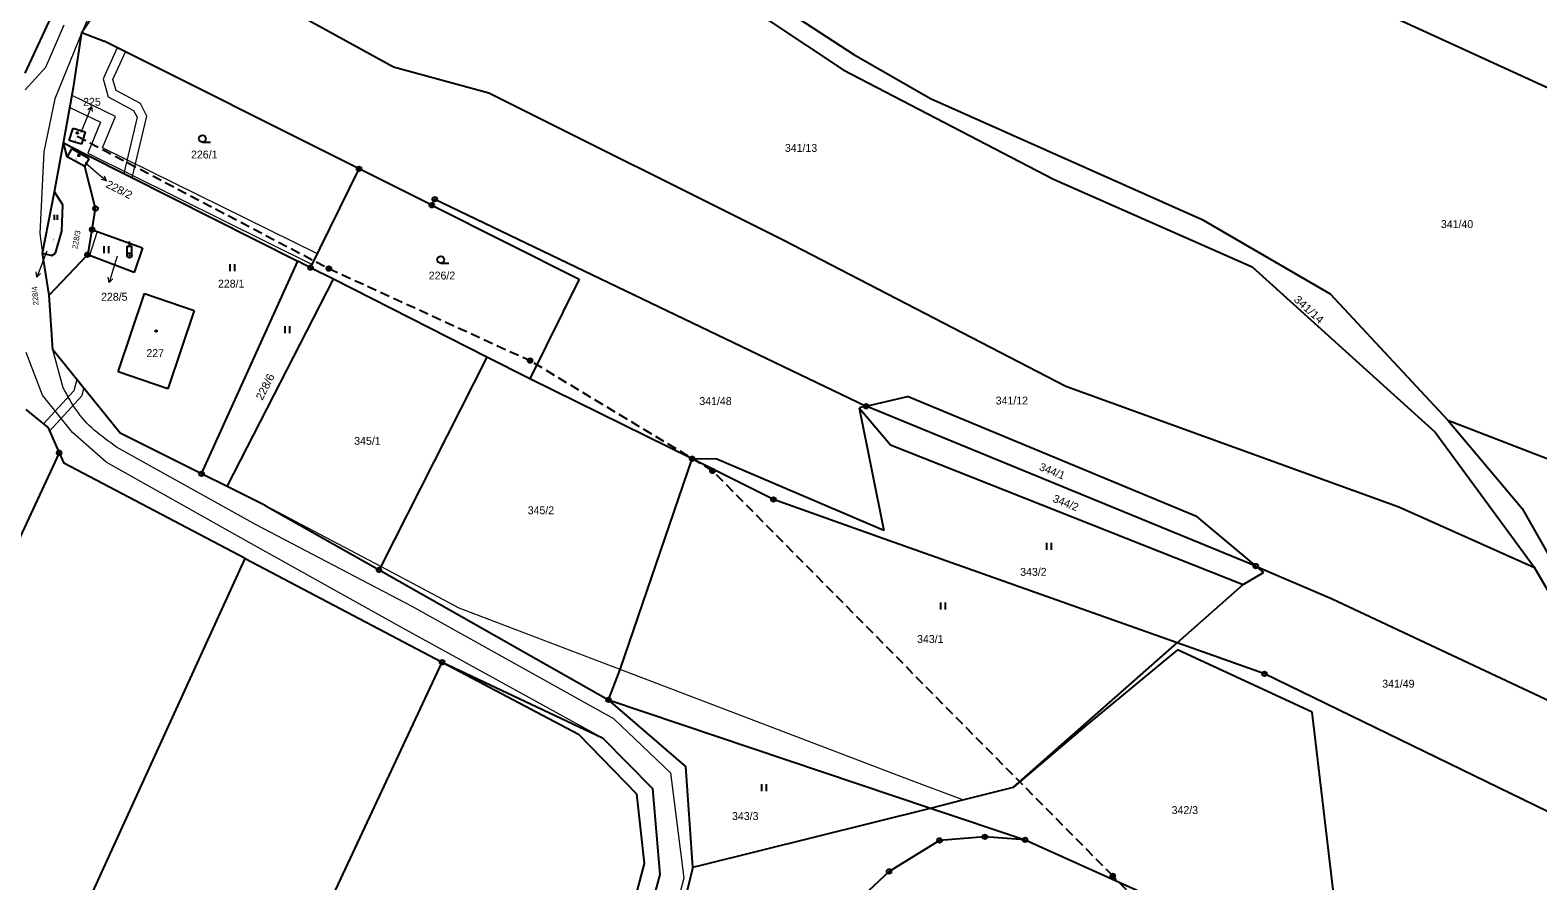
# Model space of a CAD drawing. Extents: x -504006 to -501322, y -1128098 to -1124665.
# Drawn here: x -502552.5 to -502227.9, y -1127007.5 to -1126824.4 of the extents above; entities that cross this region are included whole.
import ezdxf
from ezdxf.enums import TextEntityAlignment as Align

# ---------------------------------------------------------------- set-up
doc = ezdxf.new("R2010")
doc.units = 0
doc.header["$LTSCALE"] = 0.68
doc.linetypes.add('MEDIUM_DASHED', pattern=[4.5, 3, -1.5])
for name, color, linetype, lineweight in [('1', 7, 'Continuous', 25), ('13', 7, 'Continuous', 13), ('3', 7, 'Continuous', 25), ('4', 7, 'Continuous', 13), ('5', 7, 'Continuous', 25), ('6', 7, 'Continuous', 25), ('7', 7, 'Continuous', 13), ('8', 7, 'Continuous', 25)]:
    doc.layers.add(name, color=color, linetype=linetype, lineweight=lineweight)
doc.layers.add('2', color=7, linetype='Continuous')

msp = doc.modelspace()

# ---------------------------------------------------------------- linework, layer by layer
at = {"layer": '1'}
for p, q in [((-502305.89, -1126800.07), (-502203.09, -1126847.14)), ((-502526.88, -1126803.35), (-502541.38, -1126824.92)), ((-502526.88, -1126803.35), (-502474.26, -1126832.3)), ((-502399.9, -1126813.53), (-502375.12, -1126829.65)), ((-502401.11, -1126817.15), (-502377.47, -1126832.95)), ((-502548.07, -1126821.6), (-502553.7, -1126833.67)), ((-502541.38, -1126824.92), (-502536.58, -1126826.79)), ((-502481.7, -1126854.26), (-502536.58, -1126826.79)), ((-502375.12, -1126829.65), (-502358.67, -1126839.14)), ((-502474.26, -1126832.3), (-502453.74, -1126837.88)), ((-502377.47, -1126832.95), (-502332.18, -1126856.51)), ((-502453.74, -1126837.88), (-502390.23, -1126869.59)), ((-502358.67, -1126839.14), (-502300.15, -1126865.18)), ((-502544.09, -1126848.12), (-502543.27, -1126845.5)), ((-502543.27, -1126845.5), (-502540.64, -1126846.32)), ((-502540.64, -1126846.32), (-502541.46, -1126848.94)), ((-502547.31, -1126859.18), (-502545.37, -1126848.68)), ((-502544.56, -1126851.66), (-502545.37, -1126848.68)), ((-502545.37, -1126848.68), (-502540.43, -1126851.17)), ((-502543.61, -1126849.95), (-502544.56, -1126851.66)), ((-502541.46, -1126848.94), (-502544.09, -1126848.12)), ((-502539.81, -1126852.1), (-502543.61, -1126849.95)), ((-502540.75, -1126853.78), (-502544.56, -1126851.66)), ((-502540.75, -1126853.78), (-502539.81, -1126852.1)), ((-502538.42, -1126862.8), (-502540.75, -1126853.78)), ((-502540.43, -1126851.17), (-502494.86, -1126874.15)), ((-502492.13, -1126875.53), (-502481.7, -1126854.26)), ((-502466.04, -1126862.09), (-502481.7, -1126854.26)), ((-502332.18, -1126856.51), (-502289.41, -1126875.33)), ((-502549.83, -1126872.4), (-502547.31, -1126859.18)), ((-502545.45, -1126862), (-502547.31, -1126859.18)), ((-502545.72, -1126867.65), (-502545.45, -1126862)), ((-502539.16, -1126867.32), (-502538.42, -1126862.8)), ((-502466.04, -1126862.09), (-502465.39, -1126860.78)), ((-502466.04, -1126862.09), (-502434.27, -1126877.98)), ((-502465.39, -1126860.78), (-502372.48, -1126905.35)), ((-502300.15, -1126865.18), (-502272.6, -1126881.18)), ((-502547.06, -1126872.38), (-502545.72, -1126867.65)), ((-502540.04, -1126872.57), (-502539.16, -1126867.32)), ((-502539.16, -1126867.32), (-502538.07, -1126867.72)), ((-502538.07, -1126867.72), (-502528.33, -1126871.26)), ((-502390.23, -1126869.59), (-502329.52, -1126901.01)), ((-502548.43, -1126881.43), (-502549.83, -1126872.4)), ((-502549.83, -1126872.4), (-502547.87, -1126872.92)), ((-502548.43, -1126881.43), (-502540.19, -1126872.74)), ((-502547.87, -1126872.92), (-502547.06, -1126872.38)), ((-502540.19, -1126872.74), (-502540.04, -1126872.57)), ((-502539.77, -1126872.9), (-502540.19, -1126872.74)), ((-502530.1, -1126876.54), (-502539.77, -1126872.9)), ((-502528.33, -1126871.26), (-502530.1, -1126876.54)), ((-502515.61, -1126919.91), (-502494.86, -1126874.15)), ((-502492.13, -1126875.53), (-502494.86, -1126874.15)), ((-502487.18, -1126878.02), (-502492.13, -1126875.53)), ((-502289.41, -1126875.33), (-502249.96, -1126910.91)), ((-502510.13, -1126922.64), (-502487.18, -1126878.02)), ((-502454.16, -1126894.76), (-502487.18, -1126878.02)), ((-502434.27, -1126877.98), (-502444.93, -1126899.44)), ((-502547.64, -1126893.23), (-502548.43, -1126881.43)), ((-502533.59, -1126897.97), (-502527.88, -1126881.12)), ((-502527.88, -1126881.12), (-502517.19, -1126884.74)), ((-502272.6, -1126881.18), (-502247.28, -1126908.37)), ((-502517.19, -1126884.74), (-502522.9, -1126901.59)), ((-502533.11, -1126911.18), (-502547.64, -1126893.23)), ((-502444.93, -1126899.44), (-502454.16, -1126894.76)), ((-502522.9, -1126901.59), (-502533.59, -1126897.97)), ((-502409.98, -1126916.66), (-502444.93, -1126899.44)), ((-502329.52, -1126901.01), (-502257.82, -1126926.98)), ((-502372.48, -1126905.35), (-502374.04, -1126905.71)), ((-502374.04, -1126905.71), (-502367.28, -1126913.63)), ((-502374.04, -1126905.71), (-502368.71, -1126932.11)), ((-502372.48, -1126905.35), (-502363.59, -1126903.28)), ((-502301.37, -1126929.06), (-502363.59, -1126903.28)), ((-502548.72, -1126909.88), (-502553.35, -1126906.08)), ((-502247.28, -1126908.37), (-502231.26, -1126927.35)), ((-502247.28, -1126908.37), (-502196.45, -1126927.98)), ((-502548.72, -1126909.88), (-502546.27, -1126915.37)), ((-502515.61, -1126919.91), (-502533.11, -1126911.18)), ((-502249.96, -1126910.91), (-502228.62, -1126940.07)), ((-502546.27, -1126915.37), (-502588.67, -1127006.49)), ((-502546.27, -1126915.37), (-502545.27, -1126917.6)), ((-502506.22, -1126938.15), (-502545.27, -1126917.6)), ((-502425.46, -1126962.01), (-502409.98, -1126916.66)), ((-502392.47, -1126925.43), (-502409.98, -1126916.66)), ((-502404.67, -1126916.75), (-502409.98, -1126916.66)), ((-502368.71, -1126932.11), (-502404.67, -1126916.75)), ((-502510.13, -1126922.64), (-502515.61, -1126919.91)), ((-502501.9, -1126926.74), (-502510.13, -1126922.64)), ((-502369.91, -1126933.44), (-502392.47, -1126925.43)), ((-502501.9, -1126926.74), (-502477.4, -1126940.59)), ((-502257.82, -1126926.98), (-502228.62, -1126940.07)), ((-502231.26, -1126927.35), (-502223.47, -1126941.03)), ((-502305.51, -1126956.29), (-502369.91, -1126933.44)), ((-502569.42, -1127076.25), (-502506.22, -1126938.15)), ((-502506.22, -1126938.15), (-502463.83, -1126960.45)), ((-502477.4, -1126940.59), (-502427.98, -1126968.55)), ((-502288.61, -1126939.76), (-502286.95, -1126941.16)), ((-502288.61, -1126939.76), (-502272.17, -1126946.8)), ((-502206.84, -1126977.44), (-502228.62, -1126940.07)), ((-502305.51, -1126956.29), (-502291.29, -1126943.74)), ((-502272.17, -1126946.8), (-502206.84, -1126977.44)), ((-502340.75, -1126987.38), (-502305.51, -1126956.29)), ((-502305.44, -1126957.82), (-502324.99, -1126973.93)), ((-502286.73, -1126962.95), (-502305.51, -1126956.29)), ((-502276.45, -1126971.2), (-502305.44, -1126957.82)), ((-502517.95, -1127076.19), (-502463.83, -1126960.45)), ((-502463.83, -1126960.45), (-502429.25, -1126976.74)), ((-502463.83, -1126960.45), (-502434.41, -1126975.93)), ((-502427.98, -1126968.55), (-502425.46, -1126962.01)), ((-502187, -1127011.49), (-502286.73, -1126962.95)), ((-502411.3, -1126982.9), (-502427.98, -1126968.55)), ((-502427.98, -1126968.55), (-502358.65, -1126991.84)), ((-502324.99, -1126973.93), (-502340.75, -1126987.38)), ((-502269.52, -1127030.14), (-502276.45, -1126971.2)), ((-502434.41, -1126975.93), (-502421.93, -1126988.81)), ((-502429.25, -1126976.74), (-502418.54, -1126987.62)), ((-502409.84, -1127004.56), (-502411.3, -1126982.9)), ((-502421.93, -1126988.81), (-502420.31, -1127003.75)), ((-502418.54, -1126987.62), (-502416.95, -1127006.13)), ((-502358.65, -1126991.84), (-502351.71, -1126990.11)), ((-502351.71, -1126990.11), (-502340.75, -1126987.38)), ((-502408.04, -1127004.12), (-502358.65, -1126991.84)), ((-502358.65, -1126991.84), (-502338.27, -1126998.68)), ((-502356.68, -1126998.82), (-502367.57, -1127005.49)), ((-502346.93, -1126998.04), (-502356.68, -1126998.82)), ((-502338.27, -1126998.68), (-502346.93, -1126998.04)), ((-502338.27, -1126998.68), (-502306.39, -1127013.04)), ((-502420.31, -1127003.75), (-502447.1, -1127104.4)), ((-502416.95, -1127006.13), (-502443.22, -1127104.8)), ((-502409.84, -1127004.56), (-502434.09, -1127105.76)), ((-502409.84, -1127004.56), (-502408.04, -1127004.12)), ((-502367.57, -1127005.49), (-502385.06, -1127021.9))]:
    msp.add_line(p, q, dxfattribs=at)
for points in [[(-502545.37, -1126848.68), (-502543.17, -1126836.75), (-502541.38, -1126824.92)], [(-502454.16, -1126894.76), (-502477.04, -1126939.87), (-502477.4, -1126940.59)], [(-502301.37, -1126929.06), (-502288.61, -1126939.76), (-502372.48, -1126905.35)], [(-502367.28, -1126913.63), (-502291.29, -1126943.74), (-502286.95, -1126941.16)]]:
    msp.add_lwpolyline(points, dxfattribs=at)
at = {"layer": '13'}
for points in [[(-502533.79, -1126828.19), (-502536.82, -1126834.9), (-502535.69, -1126838.78), (-502530.24, -1126841.67), (-502529.49, -1126843.15), (-502532.36, -1126855.24), (-502530.52, -1126856.17), (-502527.37, -1126842.91), (-502528.74, -1126840.19), (-502534.01, -1126837.4), (-502534.7, -1126835.04), (-502532, -1126829.09)], [(-502543.49, -1126838.49), (-502543.96, -1126841.03), (-502537.36, -1126844.21), (-502540.12, -1126850.91), (-502491.79, -1126874.83), (-502490.68, -1126872.57), (-502536.92, -1126849.71), (-502534.15, -1126842.98)], [(-502540.93, -1126901.52), (-502542.49, -1126899.6), (-502543.13, -1126902.03), (-502549.61, -1126909.15), (-502548.72, -1126909.88), (-502548.34, -1126910.72), (-502541.33, -1126903.01)]]:
    msp.add_lwpolyline(points, close=True, dxfattribs=at)
at = {"layer": '3'}
for p, q in [((-502515.423, -1126848.49), (-502513.673, -1126848.49)), ((-502547.308, -1126865.24), (-502547.308, -1126864.19)), ((-502546.607, -1126865.24), (-502546.607, -1126864.19)), ((-502536.601, -1126872.43), (-502536.601, -1126870.93)), ((-502535.6, -1126872.43), (-502535.6, -1126870.93)), ((-502509.421, -1126876.3), (-502509.421, -1126874.8)), ((-502508.42, -1126876.3), (-502508.42, -1126874.8)), ((-502464.113, -1126874.54), (-502462.363, -1126874.54)), ((-502497.581, -1126889.62), (-502497.581, -1126888.12)), ((-502496.58, -1126889.62), (-502496.58, -1126888.12)), ((-502333.591, -1126936.26), (-502333.591, -1126934.76)), ((-502332.59, -1126936.26), (-502332.59, -1126934.76)), ((-502356.401, -1126949.11), (-502356.401, -1126947.61)), ((-502355.4, -1126949.11), (-502355.4, -1126947.61)), ((-502394.991, -1126988.18), (-502394.991, -1126986.68)), ((-502393.99, -1126988.18), (-502393.99, -1126986.68))]:
    msp.add_line(p, q, dxfattribs=at)
for centre in [(-502515.4229, -1126847.7398), (-502464.1129, -1126873.7898)]:
    msp.add_circle(centre, 0.75, dxfattribs=at)
at = {"layer": '4'}
for p, q in [((-502533.9, -1126807.6), (-502541.38, -1126824.92)), ((-502549.15, -1126832.4), (-502545.2, -1126823.24)), ((-502541.38, -1126824.92), (-502547.18, -1126839.2)), ((-502553.6, -1126837.25), (-502549.15, -1126832.4)), ((-502547.18, -1126839.2), (-502549.55, -1126850.6)), ((-502549.55, -1126850.6), (-502550.4, -1126868.2)), ((-502550.4, -1126868.2), (-502549.83, -1126872.4)), ((-502538.07, -1126867.72), (-502539.77, -1126872.9)), ((-502549.85, -1126903), (-502553.4, -1126893.8)), ((-502545.39, -1126901.39), (-502547.64, -1126893.23)), ((-502543.39, -1126911), (-502549.85, -1126903)), ((-502536.2, -1126917.3), (-502543.39, -1126911)), ((-502503.85, -1126930.85), (-502533.9, -1126914.15)), ((-502536.2, -1126917.3), (-502504.95, -1126934.9)), ((-502477.04, -1126939.87), (-502501.9, -1126926.74)), ((-502470.26, -1126948.43), (-502503.85, -1126930.85)), ((-502504.95, -1126934.9), (-502472.33, -1126953.08)), ((-502460.13, -1126948.79), (-502477.04, -1126939.87)), ((-502426.8, -1126972.66), (-502470.26, -1126948.43)), ((-502425.46, -1126962.01), (-502460.13, -1126948.79)), ((-502472.33, -1126953.08), (-502429.25, -1126976.74)), ((-502362.79, -1126985.89), (-502425.46, -1126962.01)), ((-502351.71, -1126990.11), (-502362.79, -1126985.89))]:
    msp.add_line(p, q, dxfattribs=at)
for points in [[(-502533.9, -1126914.15), (-502534.52, -1126913.705), (-502535.146, -1126913.253), (-502535.76, -1126912.805), (-502536.369, -1126912.353), (-502536.976, -1126911.89), (-502537.567, -1126911.427), (-502538.145, -1126910.958), (-502538.716, -1126910.474), (-502539.264, -1126909.987), (-502539.795, -1126909.489), (-502540.312, -1126908.973), (-502540.8, -1126908.45), (-502541.265, -1126907.914), (-502541.714, -1126907.358), (-502542.137, -1126906.797), (-502542.542, -1126906.225), (-502542.936, -1126905.637), (-502543.312, -1126905.048), (-502543.675, -1126904.451), (-502544.033, -1126903.842), (-502544.378, -1126903.235), (-502544.717, -1126902.624), (-502545.057, -1126902.004), (-502545.39, -1126901.39)], [(-502426.8, -1126972.66), (-502414.6, -1126984.27), (-502411.76, -1127006.91), (-502437.68, -1127105.38), (-502445.66, -1127147.93), (-502446.15, -1127172.16), (-502435.84, -1127204.7), (-502413.25, -1127241.73)]]:
    msp.add_lwpolyline(points, dxfattribs=at)
at = {"layer": '5'}
for centre in [(-502542.3668, -1126846.5192), (-502542.0368, -1126851.3692), (-502525.3968, -1126889.1492)]:
    msp.add_circle(centre, 0.175, dxfattribs=at)
at = {"layer": '6', "linetype": 'MEDIUM_DASHED'}
for p, q in [((-502542.37, -1126847.22), (-502488.19, -1126875.72)), ((-502488.19, -1126875.72), (-502444.86, -1126895.54)), ((-502405.57, -1126919.27), (-502444.86, -1126895.54)), ((-502319.39, -1127006.45), (-502405.57, -1126919.27)), ((-502237.21, -1127090.33), (-502319.39, -1127006.45))]:
    msp.add_line(p, q, dxfattribs=at)
at = {"layer": '6'}
for p, q in [((-502531.14, -1126870.896), (-502531.14, -1126869.896)), ((-502531.64, -1126870.896), (-502530.64, -1126870.896)), ((-502531.64, -1126872.896), (-502531.64, -1126870.896)), ((-502530.64, -1126872.896), (-502530.64, -1126870.896))]:
    msp.add_line(p, q, dxfattribs=at)
for centre, radius in [((-502531.14, -1126872.8976), 0.5), ((-502531.14, -1126872.8976), 0.0303), ((-502488.1934, -1126875.7199), 0.5), ((-502488.1934, -1126875.7199), 0.4), ((-502488.1934, -1126875.7199), 0.3), ((-502488.1934, -1126875.7199), 0.2), ((-502488.1934, -1126875.7199), 0.1), ((-502444.8634, -1126895.5399), 0.5), ((-502444.8634, -1126895.5399), 0.4), ((-502444.8634, -1126895.5399), 0.3), ((-502444.8634, -1126895.5399), 0.2), ((-502444.8634, -1126895.5399), 0.1), ((-502405.5734, -1126919.2699), 0.5), ((-502405.5734, -1126919.2699), 0.4), ((-502405.5734, -1126919.2699), 0.3), ((-502405.5734, -1126919.2699), 0.2), ((-502405.5734, -1126919.2699), 0.1), ((-502319.3934, -1127006.4499), 0.5), ((-502319.3934, -1127006.4499), 0.4), ((-502319.3934, -1127006.4499), 0.3), ((-502319.3934, -1127006.4499), 0.2), ((-502319.3934, -1127006.4499), 0.1)]:
    msp.add_circle(centre, radius, dxfattribs=at)
at = {"layer": '7'}
for p, q in [((-502539.286, -1126840.808), (-502540.125, -1126841.548)), ((-502536.115, -1126856.839), (-502536.542, -1126855.804)), ((-502551.095, -1126877.572), (-502550.269, -1126876.816)), ((-502535.517, -1126878.71), (-502534.746, -1126877.899))]:
    msp.add_line(p, q, dxfattribs=at)
for points in [[(-502541.54, -1126846.37), (-502540.41, -1126843.59), (-502539.286, -1126840.808), (-502539.197, -1126841.924)], [(-502540.64, -1126852.89), (-502538.38, -1126854.87), (-502536.115, -1126856.839), (-502537.199, -1126856.56)], [(-502548.95, -1126871.98), (-502550.02, -1126874.77), (-502551.095, -1126877.572), (-502551.204, -1126876.457)], [(-502533.79, -1126873.05), (-502534.64, -1126875.84), (-502535.517, -1126878.71), (-502535.703, -1126877.606)]]:
    msp.add_lwpolyline(points, dxfattribs=at)
at = {"layer": '8'}
for centre, radius in [((-502481.7, -1126854.2599), 0.5), ((-502481.7, -1126854.2599), 0.0303), ((-502465.39, -1126860.7799), 0.5), ((-502538.42, -1126862.7999), 0.5), ((-502538.42, -1126862.7999), 0.0303), ((-502466.04, -1126862.0899), 0.5), ((-502466.04, -1126862.0899), 0.0303), ((-502465.39, -1126860.7799), 0.0303), ((-502539.16, -1126867.3199), 0.5), ((-502539.16, -1126867.3199), 0.0303), ((-502540.19, -1126872.7399), 0.5), ((-502540.19, -1126872.7399), 0.0303), ((-502492.13, -1126875.5299), 0.5), ((-502492.13, -1126875.5299), 0.0303), ((-502372.48, -1126905.3499), 0.5), ((-502372.48, -1126905.3499), 0.0303), ((-502546.27, -1126915.3699), 0.5), ((-502546.27, -1126915.3699), 0.0303), ((-502409.98, -1126916.6599), 0.5), ((-502409.98, -1126916.6599), 0.0303), ((-502515.61, -1126919.9099), 0.5), ((-502515.61, -1126919.9099), 0.0303), ((-502392.47, -1126925.4299), 0.5), ((-502392.47, -1126925.4299), 0.0303), ((-502477.4, -1126940.5899), 0.5), ((-502477.4, -1126940.5899), 0.0303), ((-502288.61, -1126939.7599), 0.5), ((-502288.61, -1126939.7599), 0.0303), ((-502463.83, -1126960.4499), 0.5), ((-502463.83, -1126960.4499), 0.0303), ((-502286.73, -1126962.9499), 0.5), ((-502286.73, -1126962.9499), 0.0303), ((-502427.98, -1126968.5499), 0.5), ((-502427.98, -1126968.5499), 0.0303), ((-502356.68, -1126998.8199), 0.5), ((-502356.68, -1126998.8199), 0.0303), ((-502346.93, -1126998.0399), 0.5), ((-502346.93, -1126998.0399), 0.0303), ((-502338.27, -1126998.6799), 0.5), ((-502338.27, -1126998.6799), 0.0303), ((-502367.57, -1127005.4899), 0.5), ((-502367.57, -1127005.4899), 0.0303)]:
    msp.add_circle(centre, radius, dxfattribs=at)

# ---------------------------------------------------------------- texts
at = {"layer": '2'}
for s, p in [('225', (-502539.219, -1126840.675)), ('226/1', (-502515.03, -1126852.025)), ('341/13', (-502386.52, -1126850.605)), ('226/2', (-502463.84, -1126878.075)), ('227', (-502525.589, -1126894.775)), ('341/48', (-502404.94, -1126905.095)), ('341/12', (-502341.12, -1126904.975)), ('341/49', (-502257.9, -1126965.935))]:
    msp.add_text(s, height=1.7, dxfattribs=at).set_placement(p, align=Align.CENTER)
for s, height, rotation, width, p in [('225', 0.2, 342, 1.05, (-502542.8799, -1126848.1518)), ('228/2', 0.2, 330, 1.05, (-502542.5585, -1126852.3276)), ('341/14', 1.7, 318, 1.1, (-502277.7148, -1126885.1459))]:
    msp.add_text(s, height=height, rotation=rotation, dxfattribs=dict(at, width=width)).set_placement(p, align=Align.CENTER)
at = {"layer": '2', "width": 1.05}
for s, rotation, p in [('228/2', 333, (-502536.382, -1126858.122)), ('228/6', 63, (-502502.521, -1126904.212))]:
    msp.add_text(s, height=1.7, rotation=rotation, dxfattribs=at).set_placement(p)
at = {"layer": '2'}
for s, p in [('341/40', (-502248.74, -1126867.005)), ('228/1', (-502512.07, -1126879.825)), ('345/1', (-502482.74, -1126913.655)), ('345/2', (-502445.38, -1126928.595)), ('343/2', (-502339.33, -1126941.855)), ('343/1', (-502361.54, -1126956.315)), ('343/3', (-502401.38, -1126994.425)), ('342/3', (-502306.72, -1126993.135))]:
    msp.add_text(s, height=1.7, dxfattribs=at).set_placement(p)
for s, height, rotation, p in [('228/4', 0.2, 79, (-502547.3984, -1126869.6096)), ('228/3', 1.2, 80, (-502541.995, -1126869.5982)), ('344/1', 1.7, 338, (-502332.7464, -1126920.1089)), ('344/2', 1.7, 338, (-502329.8264, -1126926.9389))]:
    msp.add_text(s, height=height, rotation=rotation, dxfattribs=at).set_placement(p, align=Align.CENTER)
msp.add_text('228/4', height=1.2, rotation=94, dxfattribs=at).set_placement((-502550.9892, -1126879.5537), align=Align.RIGHT)
msp.add_text('228/5', height=1.7, dxfattribs=at).set_placement((-502531.56, -1126882.645), align=Align.RIGHT)

doc.saveas('drawing.dxf')
